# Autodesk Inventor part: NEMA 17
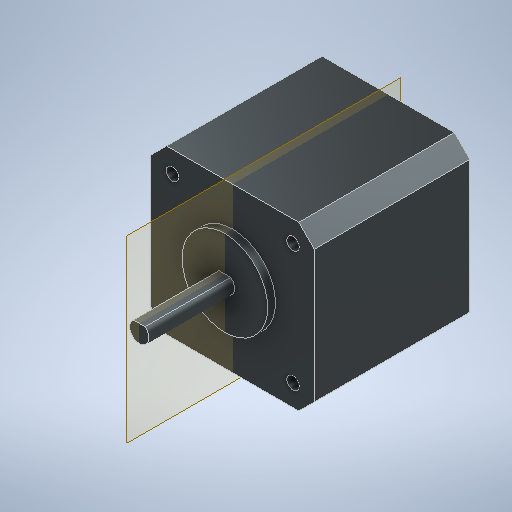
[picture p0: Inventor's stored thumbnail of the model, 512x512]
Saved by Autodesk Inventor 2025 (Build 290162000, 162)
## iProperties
Created: 2026-03
Part Number: NEMA 17
Material: Generico
Description: NEMA 17
Document SubType Name: Modeling
Designer: R5800u
Density: 1 g/cm^3
Appearance: Grigio ferro
Author: R5800u
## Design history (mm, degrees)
node "NEMA 17"
sketch "Schizzo1"
  geometry: L1 (-2.707, 42)-(39.293, 42); L2 (39.293, 42)-(39.293, 0); L3 (39.293, 0)-(-2.707, 0); L4 (-2.707, 0)-(-2.707, 42); L5 (-2.707, 42)-(39.293, 0); L6 (39.293, 42)-(-2.707, 0); L7 (50.204, 58.756)-(-13.618, 58.756); L8 (-13.618, 58.756)-(-13.618, -16.756); L9 (-13.618, -16.756)-(50.204, -16.756); L10 (50.204, -16.756)-(50.204, 58.756); L11 (50.204, 58.756)-(-13.618, -16.756); L12 (-13.618, 58.756)-(50.204, -16.756); A1 r 2.5 centre (18.293, 21) between (16.793, 23) and (19.793, 23) reference; 1 further point
  constraints: 24 end point, 4 midpoint, 4 parallel, 2 horizontal, 2 perpendicular
  dimensions: "d0" = 42 distance of L2.end L3.end; "d1" = 42 distance of L1.end L2.end
extrude "Estrusione1" cut sketch "Schizzo1" extent not by distance; stored distance "d2" = 0; taper "d3" = 0 deg
sketch "Schizzo2"
  geometry: L1 (1.5, 2)-(-1.5, 2) reference; A1 r 2.5 centre (0, 0) between (-1.5, 2) and (1.5, 2) reference; 1 further point
extrude "Estrusione2" cut sketch "Schizzo2" distance "d4" = 1; taper "d5" = 0 deg
chamfer "Smusso1" distance "d6" = 4; stored, may be unused: second distance "d7" = 2, angle "d8" = 45 deg
sketch "Schizzo3"
  geometry: L1 (38, -38)-(34, -42) reference; L2 (38, -38)-(38, -4) reference; L3 (34, 0)-(38, -4) reference; L4 (34, 0)-(0, 0) reference; L5 (-4, -4)-(0, 0) reference; L6 (-4, -4)-(-4, -38) reference; L7 (0, -42)-(-4, -38) reference; L8 (0, -42)-(34, -42) reference; C1 r 1.6 at (1.5, -5.5) reference; C2 r 1.6 at (1.5, -36.5) reference; C3 r 1.6 at (32.5, -36.5) reference; C4 r 1.6 at (32.5, -5.5) reference; 1 further point
extrude "Estrusione3" join sketch "Schizzo3" distance "d9" = 2; taper "d10" = 0 deg
sketch "Schizzo4"
  geometry: L1 (-46, 23)-(-34, 23); L2 (-34, 23)-(-34, 11); L3 (-34, 11)-(-46, 11); L4 (-46, 11)-(-46, 23); L5 (-40, 0)-(-40, 34) reference; L6 (-46, 23)-(-34, 11); L7 (-34, 23)-(-46, 11); 4 further points
  constraints: 12 end point, 3 midpoint, 2 parallel, 1 horizontal, 1 perpendicular
  dimensions: "d11" = 12 distance of L2.end L3.end; "d12" = 12 distance of L1.end L2.end
extrude "Estrusione4" join sketch "Schizzo4" distance "d13" = 4; taper "d14" = 0 deg
node "Solido1"
node "Linea chiusa proiettata1"
node "Linea chiusa proiettata2"
